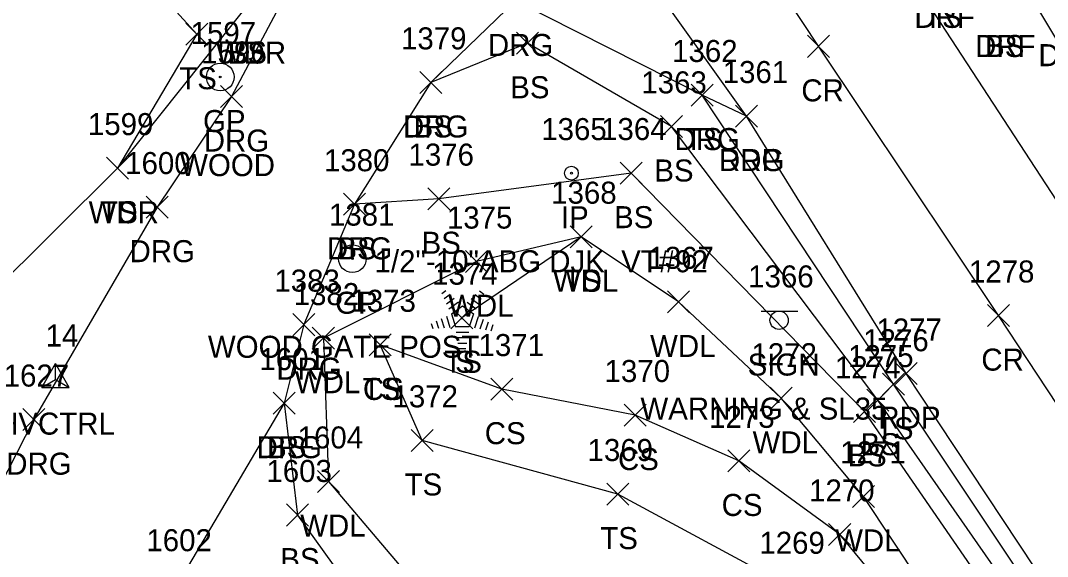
# Model space of a CAD drawing. Extents: x 1501299 to 1502485, y 381423 to 383765.
# Drawn here: x 1501656.9 to 1501750.2, y 383089.7 to 383138.3 of the extents above; entities that cross this region are included whole.
import ezdxf

# ---------------------------------------------------------------- set-up
doc = ezdxf.new("R2010")
doc.units = 0
for name, color, linetype in [('C_A', 7, 'Continuous'), ('C_I', 7, 'Continuous'), ('CPSM', 7, 'Continuous'), ('DCP', 7, 'Continuous'), ('L_A', 7, 'Continuous'), ('L_I', 7, 'Continuous'), ('L_TIC', 7, 'Continuous'), ('LAWA', 7, 'Continuous'), ('LELB', 7, 'Continuous'), ('LTC', 7, 'Continuous'), ('M_A', 7, 'Continuous'), ('M_C', 7, 'Continuous'), ('M_I', 7, 'Continuous'), ('MPIR', 7, 'Continuous'), ('P_A', 7, 'Continuous'), ('P_I', 7, 'Continuous'), ('P_TIC', 7, 'Continuous'), ('PET', 7, 'Continuous'), ('PRC', 7, 'Continuous'), ('R_A', 7, 'Continuous'), ('R_C', 7, 'Continuous'), ('R_I', 7, 'Continuous'), ('R_TIC', 7, 'Continuous'), ('RDG', 7, 'Continuous'), ('RGP', 7, 'Continuous'), ('S_A', 7, 'Continuous'), ('S_C', 7, 'Continuous'), ('S_I', 7, 'Continuous'), ('SSGN', 7, 'Continuous')]:
    doc.layers.add(name, color=color, linetype=linetype)

msp = doc.modelspace()

# ---------------------------------------------------------------- linework, layer by layer
at = {"layer": 'CPSM'}
for p, q in [((1501658.844, 383105.025), (1501660.094, 383107.19)), ((1501661.344, 383105.025), (1501660.094, 383107.19)), ((1501660.095, 383105.746), (1501660.094, 383107.19)), ((1501658.844, 383105.025), (1501660.095, 383105.746)), ((1501660.095, 383105.746), (1501660.095, 383105.746)), ((1501660.095, 383105.746), (1501661.344, 383105.025)), ((1501658.844, 383105.025), (1501661.344, 383105.025))]:
    msp.add_line(p, q, dxfattribs=at)
at = {"layer": 'DCP'}
msp.add_lwpolyline([(1501761.064, 383119.969), (1501740.356, 383154.447)], dxfattribs=at)
at = {"layer": 'L_TIC'}
for points in [[(1501671.931, 383136.106), (1501673.931, 383138.106)], [(1501673.931, 383136.106), (1501671.931, 383138.106)], [(1501701.976, 383135.285), (1501703.976, 383137.285)], [(1501703.976, 383135.285), (1501701.976, 383137.285)], [(1501693.191, 383131.723), (1501695.191, 383133.723)], [(1501695.191, 383131.723), (1501693.191, 383133.723)], [(1501717.865, 383130.579), (1501719.865, 383132.579)], [(1501719.865, 383130.579), (1501717.865, 383132.579)], [(1501715.067, 383127.727), (1501717.067, 383129.727)], [(1501717.067, 383127.727), (1501715.067, 383129.727)], [(1501664.744, 383123.938), (1501666.744, 383125.938)], [(1501666.744, 383123.938), (1501664.744, 383125.938)], [(1501664.744, 383123.938), (1501666.744, 383125.938)], [(1501666.744, 383123.938), (1501664.744, 383125.938)], [(1501711.412, 383123.491), (1501713.412, 383125.491)], [(1501713.412, 383123.491), (1501711.412, 383125.491)], [(1501693.918, 383121.167), (1501695.918, 383123.167)], [(1501695.918, 383121.167), (1501693.918, 383123.167)], [(1501686.272, 383120.659), (1501688.272, 383122.659)], [(1501688.272, 383120.659), (1501686.272, 383122.659)], [(1501706.876, 383117.713), (1501708.876, 383119.713)], [(1501708.876, 383117.713), (1501706.876, 383119.713)], [(1501706.876, 383117.713), (1501708.876, 383119.713)], [(1501708.876, 383117.713), (1501706.876, 383119.713)], [(1501697.357, 383115.453), (1501699.357, 383117.453)], [(1501699.357, 383115.453), (1501697.357, 383117.453)], [(1501715.707, 383111.798), (1501717.707, 383113.798)], [(1501717.707, 383111.798), (1501715.707, 383113.798)], [(1501696.016, 383110.359), (1501698.016, 383112.359)], [(1501698.016, 383110.359), (1501696.016, 383112.359)], [(1501683.434, 383108.505), (1501685.434, 383110.505)], [(1501685.434, 383108.505), (1501683.434, 383110.505)], [(1501688.588, 383107.897), (1501690.588, 383109.897)], [(1501690.588, 383107.897), (1501688.588, 383109.897)], [(1501688.588, 383107.897), (1501690.588, 383109.897)], [(1501690.588, 383107.897), (1501688.588, 383109.897)], [(1501735.237, 383104.316), (1501737.237, 383106.316)], [(1501737.237, 383104.316), (1501735.237, 383106.316)], [(1501699.661, 383103.877), (1501701.661, 383105.877)], [(1501701.661, 383103.877), (1501699.661, 383105.877)], [(1501679.878, 383102.605), (1501681.878, 383104.605)], [(1501681.878, 383102.605), (1501679.878, 383104.605)], [(1501725.023, 383103.042), (1501727.023, 383105.042)], [(1501727.023, 383103.042), (1501725.023, 383105.042)], [(1501733.806, 383102.876), (1501735.806, 383104.876)], [(1501735.806, 383102.876), (1501733.806, 383104.876)], [(1501711.766, 383101.523), (1501713.766, 383103.523)], [(1501713.766, 383101.523), (1501711.766, 383103.523)], [(1501732.616, 383101.86), (1501734.616, 383103.86)], [(1501734.616, 383101.86), (1501732.616, 383103.86)], [(1501692.409, 383099.221), (1501694.409, 383101.221)], [(1501694.409, 383099.221), (1501692.409, 383101.221)], [(1501721.185, 383097.36), (1501723.185, 383099.36)], [(1501723.185, 383097.36), (1501721.185, 383099.36)], [(1501683.917, 383095.489), (1501685.917, 383097.489)], [(1501685.917, 383095.489), (1501683.917, 383097.489)], [(1501710.19, 383094.349), (1501712.19, 383096.349)], [(1501712.19, 383094.349), (1501710.19, 383096.349)], [(1501732.525, 383094.142), (1501734.525, 383096.142)], [(1501734.525, 383094.142), (1501732.525, 383096.142)], [(1501681.082, 383092.448), (1501683.082, 383094.448)], [(1501683.082, 383092.448), (1501681.082, 383094.448)], [(1501730.35, 383090.675), (1501732.35, 383092.675)], [(1501732.35, 383090.675), (1501730.35, 383092.675)]]:
    msp.add_lwpolyline(points, dxfattribs=at)
at = {"layer": 'LAWA'}
for points in [[(1501548.16, 383146.636), (1501571.521, 383160.277), (1501598.465, 383173.707), (1501618.343, 383183.177), (1501640.684, 383191.304), (1501653.606, 383191.947), (1501667.482, 383171.418), (1501677.43, 383157.35), (1501677.301, 383139.435), (1501665.744, 383124.938), (1501648.242, 383107.593), (1501635.222, 383093.489)], [(1501754.165, 383064.049), (1501733.525, 383095.142), (1501726.023, 383104.042), (1501716.707, 383112.798), (1501707.876, 383118.713), (1501698.357, 383116.453), (1501684.434, 383109.505), (1501684.917, 383096.489), (1501695.37, 383084.141)]]:
    msp.add_lwpolyline(points, dxfattribs=at)
at = {"layer": 'LELB'}
for points in [[(1501574.387, 383130.876), (1501576.88, 383137.239), (1501587.123, 383134.548), (1501591.981, 383125.923), (1501605.906, 383116.295), (1501617.184, 383118.06), (1501635.069, 383129.084), (1501644.679, 383143.095), (1501638.019, 383150.194), (1501648.46, 383156.854), (1501654.993, 383162.146), (1501659.593, 383155.097), (1501663.428, 383147.565), (1501672.931, 383137.106), (1501665.744, 383124.938)], [(1501947.071, 382716.202), (1501936.789, 382745.616), (1501921.74, 382787.499), (1501900.168, 382829.778), (1501877.018, 382875.801), (1501866.166, 382892.912), (1501844.624, 382932.733), (1501828.058, 382959.038), (1501805.265, 382995.601), (1501783.687, 383028.162), (1501760.133, 383067.523), (1501734.806, 383103.876), (1501716.067, 383128.727), (1501702.976, 383136.285), (1501694.191, 383132.723)], [(1501947.958, 382716.119), (1501939.996, 382745.704), (1501923.414, 382788.324), (1501902.81, 382830.435), (1501868.959, 382893.881), (1501846.402, 382933.734), (1501830.033, 382960.147), (1501806.634, 382996.692), (1501785.685, 383029.202), (1501761.094, 383068.04), (1501736.237, 383105.316), (1501718.865, 383131.579)], [(1501945.344, 382716.136), (1501936.673, 382745.194), (1501918.388, 382786.659), (1501897.882, 382827.989), (1501871.615, 382874.073), (1501860.416, 382890.256), (1501841.87, 382931.652), (1501826.472, 382956.951), (1501803.66, 382993.76), (1501782.057, 383026.726), (1501758.572, 383066.643), (1501733.616, 383102.86), (1501712.412, 383124.491), (1501694.918, 383122.167), (1501687.272, 383121.659)], [(1501707.876, 383118.713), (1501697.016, 383111.359)], [(1501783.593, 382899.612), (1501783.944, 382929.093), (1501780.21, 382962.679), (1501777.228, 382979.105), (1501762.256, 383002.321), (1501757.64, 383021.11), (1501754.694, 383033.791), (1501751.145, 383043.326), (1501742.41, 383064.134), (1501735.879, 383077.84), (1501726.8, 383086.928), (1501711.19, 383095.349), (1501693.409, 383100.221), (1501689.588, 383108.897)], [(1501782.082, 383006.317), (1501773.809, 383019.102), (1501754.165, 383064.049), (1501731.35, 383091.675), (1501722.185, 383098.36), (1501712.766, 383102.523), (1501700.661, 383104.877), (1501689.588, 383108.897)], [(1501680.878, 383103.605), (1501682.082, 383093.448), (1501692.643, 383078.725), (1501711.231, 383076.953), (1501725.311, 383066.453), (1501722.556, 383050.376), (1501731.888, 383029.405)]]:
    msp.add_lwpolyline(points, dxfattribs=at)
at = {"layer": 'LTC'}
for p, q in [((1501695.211, 383113.567), (1501695.566, 383113.825)), ((1501698.61, 383113.808), (1501699.029, 383113.503)), ((1501695.421, 383113.102), (1501695.95, 383113.486)), ((1501695.631, 383112.636), (1501696.334, 383113.147)), ((1501695.84, 383112.17), (1501696.718, 383112.808)), ((1501697.496, 383112.763), (1501698.306, 383112.174)), ((1501697.868, 383113.111), (1501698.547, 383112.617)), ((1501698.238, 383113.459), (1501698.788, 383113.06)), ((1501696.065, 383111.715), (1501697.076, 383112.45)), ((1501697.076, 383112.45), (1501698.073, 383111.725)), ((1501694.244, 383110.847), (1501694.396, 383110.379)), ((1501694.699, 383111.063), (1501694.911, 383110.412)), ((1501695.155, 383111.28), (1501695.426, 383110.444)), ((1501695.61, 383111.496), (1501695.941, 383110.477)), ((1501696.065, 383111.715), (1501696.452, 383110.522)), ((1501698.073, 383111.725), (1501697.682, 383110.522)), ((1501698.511, 383111.454), (1501698.173, 383110.414)), ((1501698.956, 383111.204), (1501698.668, 383110.319)), ((1501699.4, 383110.954), (1501699.163, 383110.224)), ((1501697.682, 383110.522), (1501696.452, 383110.522)), ((1501697.644, 383110.022), (1501696.499, 383110.022)), ((1501699.844, 383110.703), (1501699.658, 383110.129)), ((1501697.56, 383109.522), (1501696.572, 383109.522)), ((1501697.476, 383109.022), (1501696.645, 383109.022)), ((1501697.393, 383108.522), (1501696.718, 383108.522))]:
    msp.add_line(p, q, dxfattribs=at)
at = {"layer": 'MPIR'}
for radius in [0.625, 0.0833]:
    msp.add_circle((1501706.976, 383124.485), radius, dxfattribs=at)
at = {"layer": 'P_TIC'}
for points in [[(1501728.435, 383135.001), (1501730.435, 383137.001)], [(1501730.435, 383135.001), (1501728.435, 383137.001)], [(1501721.895, 383128.668), (1501723.895, 383130.668)], [(1501723.895, 383128.668), (1501721.895, 383130.668)], [(1501744.791, 383110.558), (1501746.791, 383112.558)], [(1501746.791, 383110.558), (1501744.791, 383112.558)], [(1501736.378, 383105.292), (1501738.378, 383107.292)], [(1501738.378, 383105.292), (1501736.378, 383107.292)]]:
    msp.add_lwpolyline(points, dxfattribs=at)
at = {"layer": 'PET'}
for points in [[(1501787.994, 383066.094), (1501768.484, 383096.751), (1501754.41, 383116.891), (1501736.241, 383144.717), (1501720.749, 383167.971), (1501712.594, 383179.719), (1501694.383, 383207.646), (1501673.597, 383237.523), (1501647.754, 383273.845), (1501633.679, 383294.635), (1501626.393, 383287.881), (1501619.162, 383281.8), (1501626.926, 383271.201), (1501654.425, 383229.168), (1501675.697, 383198.288), (1501696.699, 383166.339)], [(1501949.648, 382716.507), (1501941.04, 382745.977), (1501925.012, 382788.592), (1501904.253, 382831.621), (1501880.763, 382877.887), (1501870.565, 382894.723), (1501847.406, 382934.273), (1501830.938, 382961.01), (1501807.981, 382997.987), (1501787.075, 383029.946), (1501762.257, 383068.782), (1501737.378, 383106.292), (1501722.895, 383129.668), (1501696.699, 383166.339)]]:
    msp.add_lwpolyline(points, dxfattribs=at)
at = {"layer": 'PRC'}
msp.add_lwpolyline([(1501960.612, 382718.648), (1501950.96, 382750.482), (1501934.965, 382791.852), (1501913.074, 382836.935), (1501889.309, 382881.383), (1501879.244, 382899.507), (1501856.391, 382940.32), (1501839.674, 382966.998), (1501816.055, 383004.313), (1501794.783, 383036.247), (1501769.812, 383075.158), (1501745.791, 383111.558), (1501729.435, 383136.001), (1501711.236, 383163.535), (1501694.816, 383188.199), (1501683.547, 383204.004), (1501664.644, 383231.239), (1501639.517, 383268.342), (1501626.393, 383287.881)], dxfattribs=at)
at = {"layer": 'R_TIC'}
for points in [[(1501693.191, 383131.723), (1501695.191, 383133.723)], [(1501695.191, 383131.723), (1501693.191, 383133.723)], [(1501675.082, 383130.445), (1501677.082, 383132.445)], [(1501677.082, 383130.445), (1501675.082, 383132.445)], [(1501717.865, 383130.579), (1501719.865, 383132.579)], [(1501719.865, 383130.579), (1501717.865, 383132.579)], [(1501721.895, 383128.668), (1501723.895, 383130.668)], [(1501723.895, 383128.668), (1501721.895, 383130.668)], [(1501668.335, 383120.403), (1501670.335, 383122.403)], [(1501670.335, 383120.403), (1501668.335, 383122.403)], [(1501686.272, 383120.659), (1501688.272, 383122.659)], [(1501688.272, 383120.659), (1501686.272, 383122.659)], [(1501681.676, 383109.731), (1501683.676, 383111.731)], [(1501683.676, 383109.731), (1501681.676, 383111.731)], [(1501679.878, 383102.605), (1501681.878, 383104.605)], [(1501681.878, 383102.605), (1501679.878, 383104.605)], [(1501657.131, 383101.109), (1501659.131, 383103.109)], [(1501659.131, 383101.109), (1501657.131, 383103.109)]]:
    msp.add_lwpolyline(points, dxfattribs=at)
at = {"layer": 'RDG'}
for points in [[(1501662.064, 383199.174), (1501675.115, 383176.658), (1501684.586, 383158.077), (1501685.539, 383149.226), (1501676.082, 383131.445), (1501669.335, 383121.403), (1501658.131, 383102.109), (1501647.896, 383082.123)], [(1501722.895, 383129.668), (1501718.865, 383131.579), (1501701.897, 383140.126), (1501694.191, 383132.723), (1501687.272, 383121.659), (1501682.676, 383110.731), (1501680.878, 383103.605), (1501671.174, 383087.161), (1501662.91, 383067.619)]]:
    msp.add_lwpolyline(points, dxfattribs=at)
at = {"layer": 'RGP'}
for p, q in [((1501675.071, 383133.217), (1501675.071, 383133.217)), ((1501687.072, 383116.721), (1501687.072, 383116.721))]:
    msp.add_line(p, q, dxfattribs=at)
for centre, radius in [((1501675.071, 383133.217), 1.25), ((1501675.071, 383133.217), 0.0833), ((1501687.072, 383116.721), 1.25), ((1501687.072, 383116.721), 0.0833)]:
    msp.add_circle(centre, radius, dxfattribs=at)
at = {"layer": 'SSGN'}
for p, q in [((1501724.203, 383111.963), (1501727.536, 383111.963)), ((1501725.85, 383111.129), (1501725.85, 383111.129))]:
    msp.add_line(p, q, dxfattribs=at)
msp.add_circle((1501725.85, 383111.129), 0.833, dxfattribs=at)

# ---------------------------------------------------------------- texts
at = {"layer": 'C_A'}
msp.add_text('HVCTRL', height=2, dxfattribs=at).set_placement((1501654.788, 383100.746))
at = {"layer": 'C_I'}
msp.add_text('14', height=2, dxfattribs=at).set_placement((1501659.197, 383108.746))
at = {"layer": 'L_A'}
for s, p in [('TS', (1501739.016, 383137.674)), ('BS', (1501744.562, 383135.03)), ('WDR', (1501674.663, 383134.435)), ('BS', (1501675.742, 383134.435)), ('TS', (1501671.341, 383132.106)), ('BS', (1501701.417, 383131.285)), ('BS', (1501692.632, 383127.723)), ('TS', (1501717.274, 383126.579)), ('BS', (1501714.508, 383123.727)), ('WDR', (1501663.106, 383119.938)), ('TS', (1501664.153, 383119.938)), ('BS', (1501710.853, 383119.491)), ('BS', (1501685.713, 383116.659)), ('BS', (1501693.359, 383117.167)), ('WDL', (1501705.293, 383113.713)), ('TS', (1501706.285, 383113.713)), ('WDL', (1501695.774, 383111.453)), ('WDL', (1501714.124, 383107.798)), ('TS', (1501695.426, 383106.359)), ('S', (1501696.402, 383106.359)), ('WDL', (1501681.852, 383104.505)), ('TS', (1501687.998, 383103.897)), ('CS', (1501688.029, 383103.897)), ('CS', (1501699.102, 383099.877)), ('TS', (1501734.646, 383100.316)), ('BS', (1501679.319, 383098.605)), ('WDL', (1501723.44, 383099.042)), ('BS', (1501733.247, 383098.876)), ('BS', (1501732.057, 383097.86)), ('CS', (1501711.207, 383097.523)), ('TS', (1501691.819, 383095.221)), ('CS', (1501720.626, 383093.36)), ('WDL', (1501682.334, 383091.489)), ('TS', (1501709.599, 383090.349)), ('WDL', (1501730.943, 383090.142)), ('BS', (1501680.523, 383088.448))]:
    msp.add_text(s, height=2, dxfattribs=at).set_placement(p)
at = {"layer": 'L_I'}
for s, p in [('1379', (1501691.491, 383135.723)), ('1362', (1501716.125, 383134.579)), ('1363', (1501713.327, 383131.727)), ('1599', (1501663.043, 383127.938)), ('1599', (1501663.043, 383127.938)), ('1364', (1501709.672, 383127.491)), ('1376', (1501692.17, 383125.167)), ('1380', (1501684.492, 383124.659)), ('1368', (1501705.136, 383121.713)), ('1368', (1501705.136, 383121.713)), ('1375', (1501695.664, 383119.453)), ('1367', (1501713.967, 383115.798)), ('1374', (1501694.324, 383114.359)), ('1374', (1501694.324, 383114.359)), ('1382', (1501681.742, 383112.505)), ('1373', (1501686.896, 383111.897)), ('1373', (1501686.896, 383111.897)), ('1371', (1501698.535, 383107.877)), ('1276', (1501733.489, 383108.316)), ('1272', (1501723.33, 383107.042)), ('1601', (1501678.626, 383106.605)), ('1275', (1501732.113, 383106.876)), ('1370', (1501709.986, 383105.523)), ('1274', (1501730.923, 383105.86)), ('1372', (1501690.717, 383103.221)), ('1273', (1501719.492, 383101.36)), ('1604', (1501682.098, 383099.489)), ('1369', (1501708.442, 383098.349)), ('1271', (1501731.399, 383098.142)), ('1603', (1501679.263, 383096.448)), ('1270', (1501728.571, 383094.675)), ('1269', (1501724.052, 383089.928))]:
    msp.add_text(s, height=2, dxfattribs=at).set_placement(p)
at = {"layer": 'LTC'}
msp.add_text('.', height=1.037, rotation=270, dxfattribs=at).set_placement((1501696.959, 383111.463))
at = {"layer": 'M_A'}
msp.add_text('IP', height=2, dxfattribs=at).set_placement((1501706.023, 383119.485))
at = {"layer": 'M_C'}
msp.add_text('1/2"-10"ABG DJK  VT#92', height=2, dxfattribs=at).set_placement((1501689.087, 383115.485))
at = {"layer": 'M_I'}
msp.add_text('1365', height=2, dxfattribs=at).set_placement((1501704.236, 383127.485))
at = {"layer": 'P_A'}
for s, p in [('CR', (1501727.868, 383131.001)), ('RDP', (1501720.383, 383124.668)), ('CR', (1501744.224, 383106.558)), ('RDP', (1501734.866, 383101.292))]:
    msp.add_text(s, height=2, dxfattribs=at).set_placement(p)
at = {"layer": 'P_I'}
for s, p in [('1361', (1501720.722, 383132.668)), ('1278', (1501743.098, 383114.558)), ('1277', (1501734.685, 383109.292))]:
    msp.add_text(s, height=2, dxfattribs=at).set_placement(p)
at = {"layer": 'R_A'}
for s, p in [('DRF', (1501738.141, 383137.674)), ('DRG', (1501699.385, 383135.126)), ('DRF', (1501743.657, 383135.03)), ('DRF', (1501749.403, 383134.198)), ('GP', (1501673.504, 383128.217)), ('DRG', (1501691.68, 383127.723)), ('DRG', (1501716.353, 383126.579)), ('DRG', (1501673.57, 383126.445)), ('DRG', (1501720.383, 383124.668)), ('DRG', (1501666.823, 383116.403)), ('DRG', (1501684.76, 383116.659)), ('GP', (1501685.505, 383111.721)), ('DRG', (1501680.164, 383105.731)), ('DRG', (1501678.366, 383098.605)), ('DRG', (1501655.62, 383097.109))]:
    msp.add_text(s, height=2, dxfattribs=at).set_placement(p)
at = {"layer": 'R_C'}
for s, p in [('WOOD', (1501671.425, 383124.217)), ('WOOD GATE POST', (1501673.947, 383107.721))]:
    msp.add_text(s, height=2, dxfattribs=at).set_placement(p)
at = {"layer": 'R_I'}
for s, p in [('1597', (1501672.378, 383136.217)), ('1379', (1501691.491, 383135.723)), ('1596', (1501673.334, 383134.445)), ('1362', (1501716.125, 383134.579)), ('1361', (1501720.722, 383132.668)), ('1600', (1501666.43, 383124.403)), ('1380', (1501684.492, 383124.659)), ('1381', (1501684.947, 383119.721)), ('1383', (1501679.983, 383113.731)), ('1601', (1501678.626, 383106.605)), ('1627', (1501655.391, 383105.109)), ('1602', (1501668.355, 383090.161))]:
    msp.add_text(s, height=2, dxfattribs=at).set_placement(p)
at = {"layer": 'S_A'}
msp.add_text('SIGN', height=2, dxfattribs=at).set_placement((1501722.988, 383106.109))
at = {"layer": 'S_C'}
msp.add_text('WARNING & SL35', height=2, dxfattribs=at).set_placement((1501713.248, 383102.109))
at = {"layer": 'S_I'}
msp.add_text('1366', height=2, dxfattribs=at).set_placement((1501723.035, 383114.109))

doc.saveas('drawing.dxf')
